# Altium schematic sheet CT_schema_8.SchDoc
size 254 x 194 mm
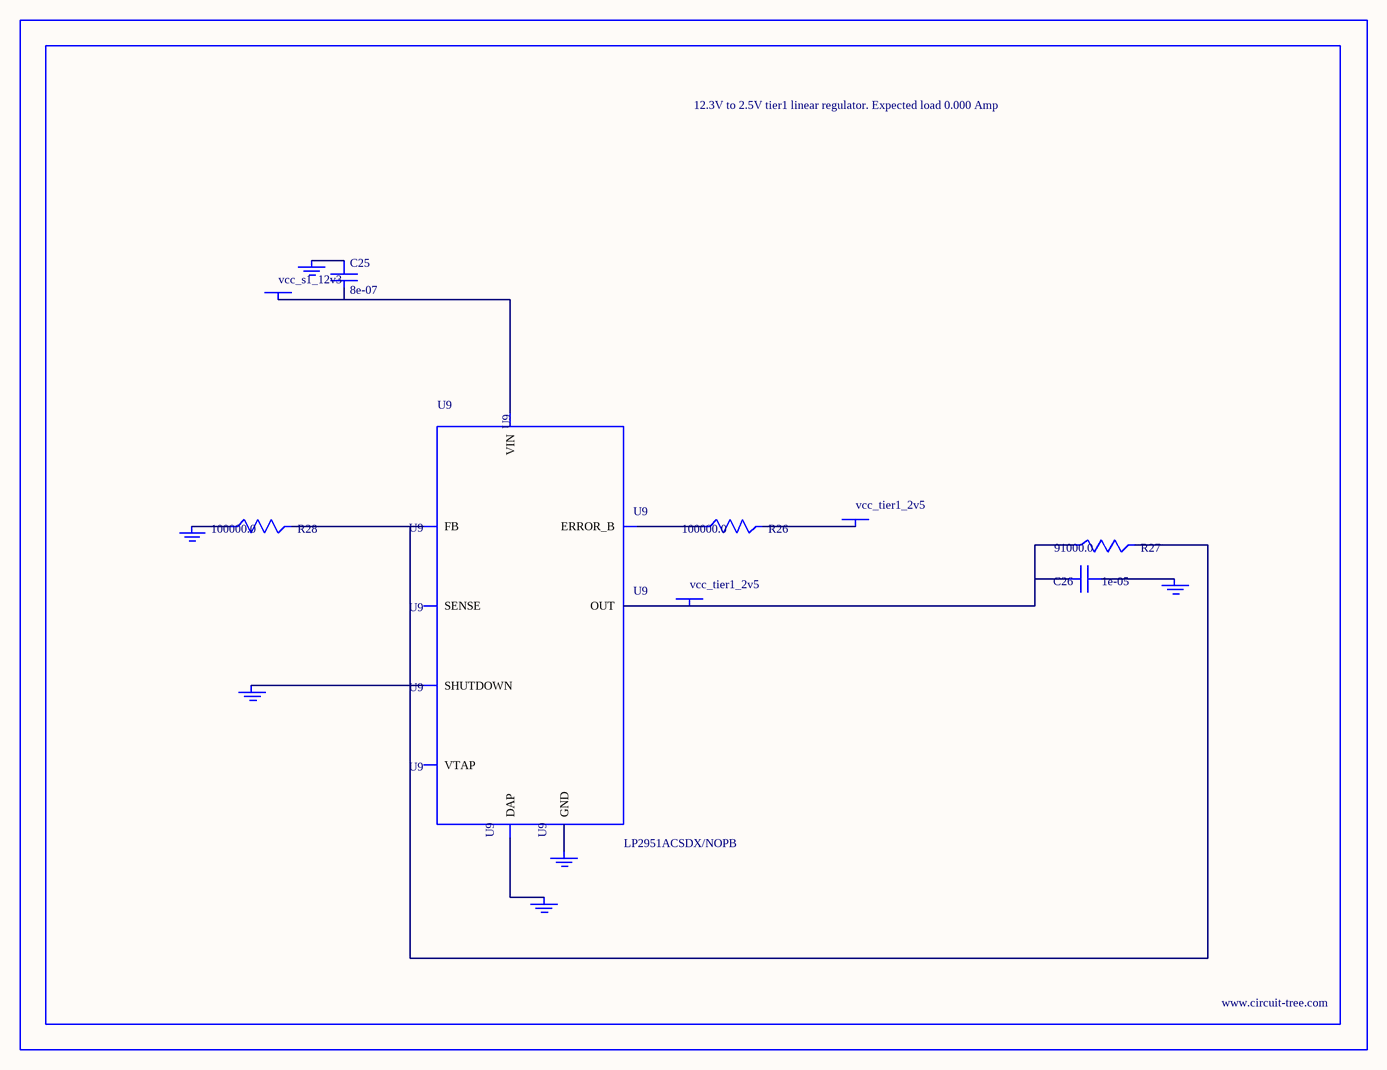
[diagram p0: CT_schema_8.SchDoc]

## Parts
BORDER7  (no value)
C25  8e-07  [R0603]
C26  1e-05  [C1210]
GND_INSTANCE_7_0  (no value)
GND_INSTANCE_7_1  (no value)
GND_INSTANCE_7_2  (no value)
GND_INSTANCE_7_3  (no value)
GND_INSTANCE_7_4  (no value)
GND_INSTANCE_7_5  (no value)
POWER_INSTANCE_7_0  vcc_tier1_2v5
POWER_INSTANCE_7_1  vcc_s1_12v3
POWER_INSTANCE_7_2  vcc_tier1_2v5
R26  100000.0  [R0603]
R27  91000.0  [R0603]
R28  100000.0  [R0603]
U9  LP2951ACSDX/NOPB  [WSON-8]

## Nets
NetC25_1: C25.1 GND_INSTANCE_7_3.0(GND)
NetC25_2: C25.2 POWER_INSTANCE_7_1.0(PWR) U9.8(VIN)
NetC26_1: C26.1 GND_INSTANCE_7_0.0(GND)
NetC26_2: C26.2 POWER_INSTANCE_7_2.0(PWR) R27.1 U9.1(OUT)
NetGND_INSTANCE_7_1_0: GND_INSTANCE_7_1.0(GND) U9.3(SHUTDOWN)
NetGND_INSTANCE_7_2_0: GND_INSTANCE_7_2.0(GND) R28.1
NetGND_INSTANCE_7_4_0: GND_INSTANCE_7_4.0(GND) U9.PAD(DAP)
NetGND_INSTANCE_7_5_0: GND_INSTANCE_7_5.0(GND) U9.4(GND)
NetPOWER_INSTANCE_7_0_0: POWER_INSTANCE_7_0.0(PWR) R26.2
NetR26_1: R26.1 U9.5(ERROR_B)
NetR27_2: R27.2 R28.2 U9.7(FB)

Not connected (* = marked no-connect by the designer): U9 2(SENSE) 6(VTAP)

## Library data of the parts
BORDER7 = BORDER_PAGE7
C25 = C25
C26 = GRM32DR61E106MA12L
GND_INSTANCE_7_0-GND_INSTANCE_7_5 = GND
POWER_INSTANCE_7_0-POWER_INSTANCE_7_2 = PWR
R26 R28 = RC0603JR-07100KL
R27 = RC0603JR-0791KL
